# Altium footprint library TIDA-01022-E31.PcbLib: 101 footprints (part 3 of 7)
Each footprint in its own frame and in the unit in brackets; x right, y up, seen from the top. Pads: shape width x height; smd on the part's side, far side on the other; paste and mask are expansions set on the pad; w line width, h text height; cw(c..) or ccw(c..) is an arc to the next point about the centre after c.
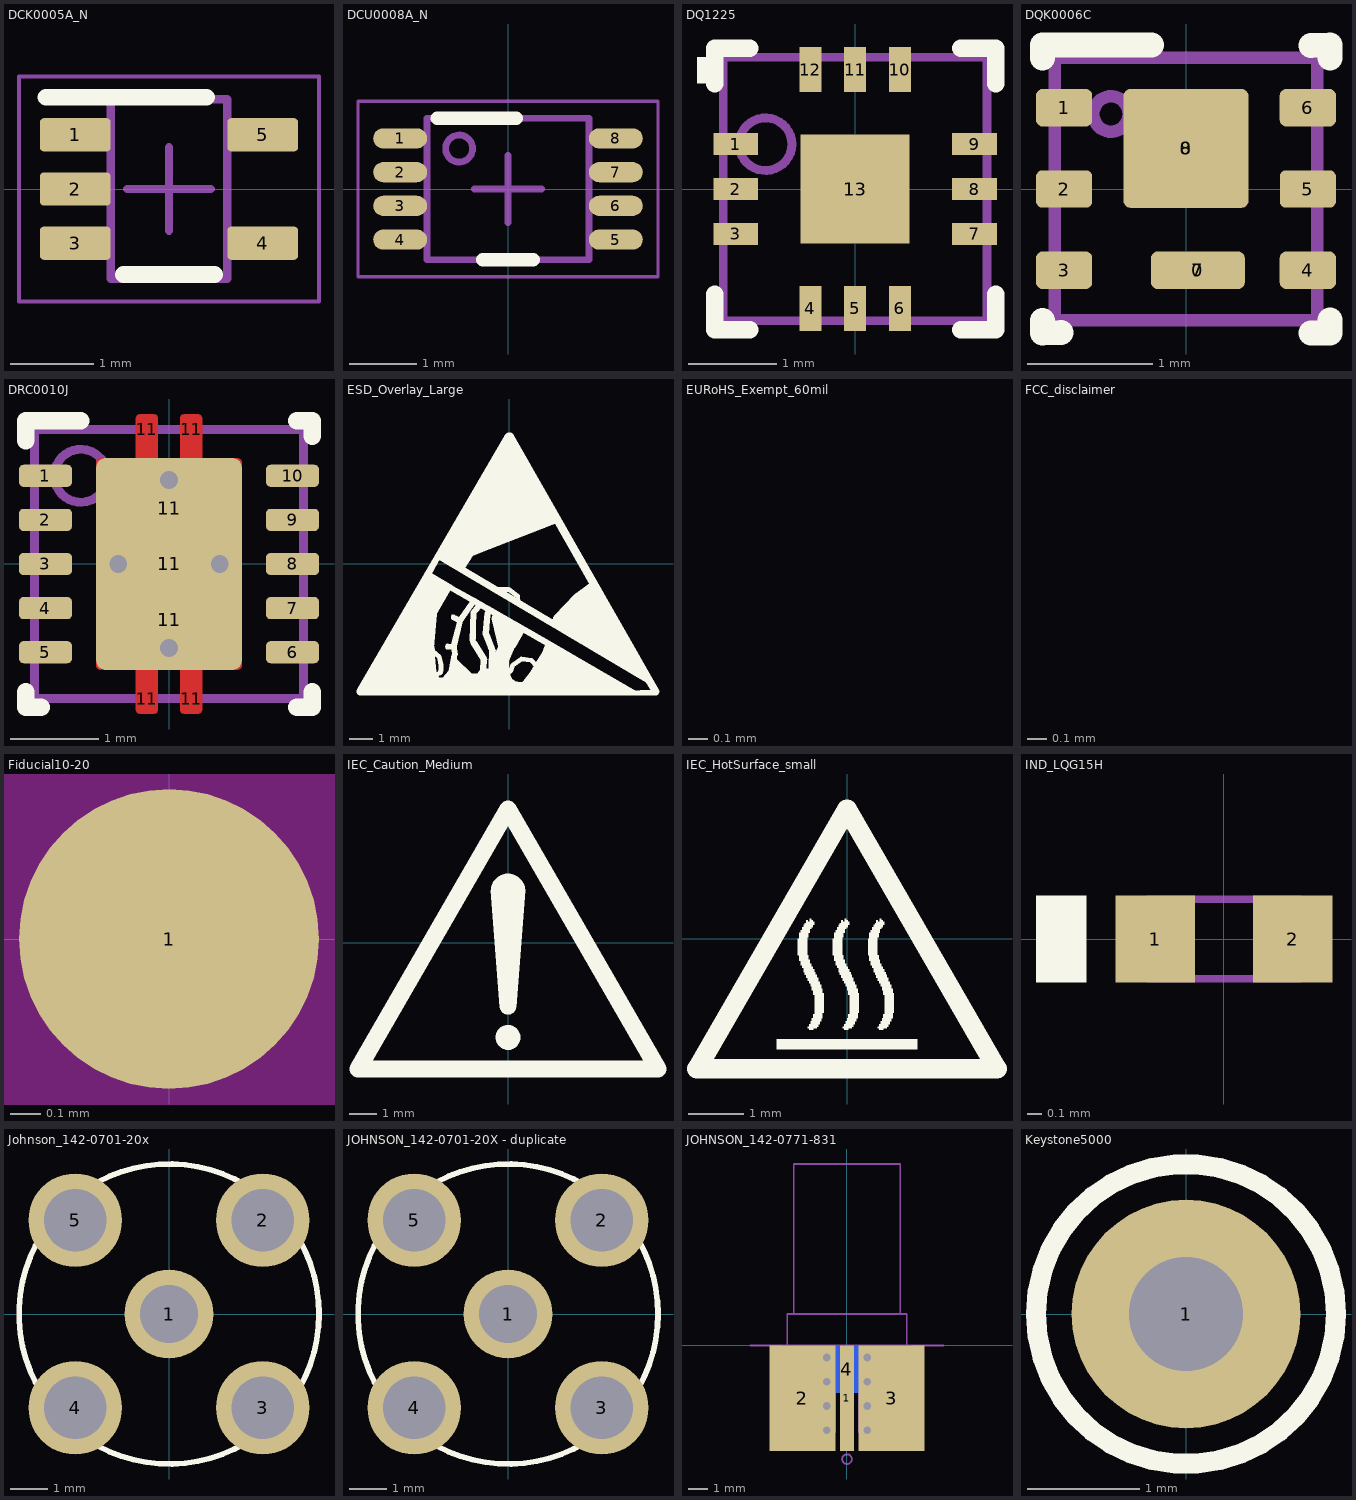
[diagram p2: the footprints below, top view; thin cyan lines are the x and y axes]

## DCK0005A_N [mm] "SOT353, 5-Leads, Body 2x1.3mm, Pitch 0.65mm, Lead Span 2.1mm, IPC Medium Density"
height 1.1
pads (5):
  rrect25% 0.85x0.4 smd: 1(10.178,0.65) 2(10.178,0) 3(10.178,-0.65) 4(12.428,-0.65) 5(12.428,0.65)
Top Overlay:
  lines w0.2: 9.828,1.1 11.753,1.1 ; 10.753,-1.025 11.853,-1.025
Mechanical 5:
  lines w0.1: 10.603,-1.075 12.003,-1.075 12.003,1.075 10.603,1.075 10.603,-1.075
  lines w0.127: 10.438,0.762 10.45,0.762 ; 10.592,-0.763 10.45,-0.763 10.438,-0.763 10.344,-0.763 10.16,-0.763 10.16,-0.538 10.344,-0.538 10.438,-0.538 10.45,-0.538 10.592,-0.538 ; 10.592,-0.113 10.45,-0.113 10.438,-0.113 10.344,-0.113 10.16,-0.113 10.16,0.112 10.344,0.112 10.438,0.112 10.45,0.112 10.592,0.112 ; 10.592,0.537 10.45,0.537 10.438,0.537 10.344,0.537 10.16,0.537 10.16,0.762 10.344,0.762 10.592,0.762 ; 12.014,-0.763 12.15,-0.763 12.162,-0.763 12.256,-0.763 12.44,-0.763 12.44,-0.538 12.256,-0.538 12.162,-0.538 12.15,-0.538 12.014,-0.538 ; 12.014,0.537 12.15,0.537 12.162,0.537 12.256,0.537 12.44,0.537 12.44,0.762 12.256,0.762 12.162,0.762 12.15,0.762 12.014,0.762
  text ".Designator" at 11.046,0.618 h0.51
Mechanical 15:
  lines w0.05: 9.503,-1.35 13.103,-1.35 13.103,1.35 9.503,1.35 9.503,-1.35
  lines w0.1: 10.803,0 11.803,0 ; 11.303,-0.5 11.303,0.5
3D body "DCK0005A.stp": height 0.95, standoff 0, extent 10.163,-1 12.443,1

## DCU0008A_N [mm] "TSSOP, 8-Leads, Body 2x2.3mm, Pitch 0.5mm, IPC Medium Density"
height 0.9
pads (8):
  oval 0.8x0.3 smd: 1(-1.6,0.75) 2(-1.6,0.25) 3(-1.6,-0.25) 4(-1.6,-0.75) 5(1.6,-0.75) 6(1.6,-0.25) 7(1.6,0.25) 8(1.6,0.75)
Top Overlay:
  lines w0.2: -1.05,1.05 0.125,1.05 ; -0.375,-1.05 0.375,-1.05
Mechanical 5:
  circle w0.1: c-0.725,0.6 r0.2
  lines w0.1: -1.2,-1.05 1.2,-1.05 1.2,1.05 -1.2,1.05 -1.2,-1.05
  text ".Designator" at 0.635,-0.127 h0.51
Mechanical 15:
  lines w0.05: -2.225,-1.3 -2.225,1.3 2.225,1.3 2.225,-1.3 -2.225,-1.3
  lines w0.1: -0.5,0 0.5,0 ; 0,-0.5 0,0.5
3D body "DCU0008A.stp": height 0.9, standoff 0, extent -1.561,-1 1.561,1

## DQ1225 [mm] "SMD, 12-Leads, Body 3x3mm"
height 0.89
pads (13):
  rect 0.51x0.25 smd: 1(-1.36,0.51) 2(-1.36,0) 3(-1.36,-0.51) 7(1.36,-0.51) 8(1.36,0) 9(1.36,0.51)
  rect 0.25x0.51 smd: 4(-0.51,-1.36) 5(0,-1.36) 6(0.51,-1.36) 10(0.51,1.36) 11(0,1.36) 12(-0.51,1.36)
  rect 1.24x1.24 smd: 13(0,0)
Top Overlay:
  rectangle: -1.8,1.2 -1.6,1.5
  lines w0.2: -1.6,-1.2 -1.6,-1.6 -1.2,-1.6 ; -1.6,1.2 -1.6,1.6 -1.2,1.6 ; 1.2,-1.6 1.6,-1.6 1.6,-1.2 ; 1.2,1.6 1.6,1.6 1.6,1.2
Mechanical 5:
  circle w0.1: c-1.02,0.51 r0.3
  lines w0.1: -1.5,-1.5 -1.5,1.5 1.5,1.5 1.5,-1.5 -1.5,-1.5
  text ".Designator" at -1.02,-0.51 h0.51
3D body: height 0.89, standoff 0, extent -1.5,-1.5 1.5,1.5
3D body: height 0.89, standoff 0.89, extent -1.319,0.211 -0.721,0.809

## DQK0006C [mm] "WSON"
height 0.8
pads (10):
  rrect50% 0.9x0.86 on Top Paste: 0(0,0.325)
  rrect50% 0.7x0.29 on Top Paste: 0(0.095,-0.65)
  rrect33% 0.45x0.3 smd: 1(-0.975,0.65) 2(-0.975,0) 3(-0.975,-0.65) 4(0.975,-0.65) 5(0.975,0) 6(0.975,0.65)
  rrect33% 0.75x0.3 smd paste-0.15: 7(0.095,-0.65)
  rrect11% 1x0.95 smd paste-0.5: 8(0,0.325)
Top Overlay:
  lines w0.2: -1.15,-1.05 -1.15,-1.15 -1,-1.15 ; -1.15,1.05 -1.15,1.15 -0.275,1.15 ; 1,-1.15 1.15,-1.15 1.15,-1.05 ; 1,1.15 1.15,1.15 1.15,1.05
Mechanical 5:
  circle w0.1: c-0.6,0.6 r0.141
  lines w0.1: -1.05,-1.05 1.05,-1.05 1.05,1.05 -1.05,1.05 -1.05,-1.05
  text ".Designator" at 0.267,-0.533 h0.51
3D body "DQK0006C.stp": height 0.82, standoff 0, extent -1,-1 1,1

## DRC0010J [mm] "SON, 10-Leads, Body 3x3mm, Pitch 0.5mm, Thermal Pad 2.4x1.65mm, TI Recommended"
height 1
pads (17):
  rrect40% 0.6x0.25 smd: 1(-1.4,1) 2(-1.4,0.5) 3(-1.4,0) 4(-1.4,-0.5) 5(-1.4,-1) 6(1.4,-1) 7(1.4,-0.5) 8(1.4,0) 9(1.4,0.5) 10(1.4,1)
  rrect50% 0.25x0.34 on Top Paste: 11(-0.25,-1.53) 11(-0.25,1.53) 11(0.25,-1.53) 11(0.25,1.53)
  rrect50% 1.5x1.06 on Top Paste: 11(0,-0.63) 11(0,0.63)
  rrect12% 1.65x2.4 smd paste-1 mask-2: 11(0,0)
via 0,-0.95 diameter 0.406 hole 0.203
via 0,0.95 diameter 0.406 hole 0.203
via -0.575,0 diameter 0.406 hole 0.203
via 0.575,0 diameter 0.406 hole 0.203
Top Layer:
  region: -0.775,-1.2 -0.375,-1.2 -0.375,-1.65 -0.375,-1.66 -0.367,-1.678 -0.353,-1.692 -0.335,-1.7 -0.325,-1.7 -0.175,-1.7 -0.165,-1.7 -0.147,-1.692 -0.133,-1.678 -0.125,-1.66 -0.125,-1.65 -0.125,-1.2 0.125,-1.2 0.125,-1.65 0.125,-1.66 0.133,-1.678 0.147,-1.692 0.165,-1.7 0.175,-1.7 0.325,-1.7 0.335,-1.7 0.353,-1.692 0.367,-1.678 0.375,-1.66 0.375,-1.65 0.375,-1.2 0.775,-1.2 0.785,-1.2 0.803,-1.192 0.817,-1.178 0.825,-1.16 0.825,-1.15 0.825,1.15 0.825,1.16 0.817,1.178 0.803,1.192 0.785,1.2 0.775,1.2 0.375,1.2 0.375,1.65 0.375,1.66 0.367,1.678 0.353,1.692 0.335,1.7 0.325,1.7 0.175,1.7 0.165,1.7 0.147,1.692 0.133,1.678 0.125,1.66 0.125,1.65 0.125,1.2 -0.125,1.2 -0.125,1.65 -0.125,1.66 -0.133,1.678 -0.147,1.692 -0.165,1.7 -0.175,1.7 -0.325,1.7 -0.335,1.7 -0.353,1.692 -0.367,1.678 -0.375,1.66 -0.375,1.65 -0.375,1.2 -0.775,1.2 -0.785,1.2 -0.803,1.192 -0.817,1.178 -0.825,1.16 -0.825,1.15 -0.825,-1.15 -0.825,-1.16 -0.817,-1.178 -0.803,-1.192 -0.785,-1.2
Top Overlay:
  lines w0.2: -1.625,-1.45 -1.625,-1.625 -1.45,-1.625 ; -1.625,1.4 -1.625,1.625 -1,1.625 ; 1.45,-1.625 1.625,-1.625 1.625,-1.45 ; 1.45,1.625 1.625,1.625 1.625,1.45
Mechanical 5:
  circle w0.1: c-1,1 r0.3
  lines w0.1: -1.525,-1.525 -1.525,1.525 1.525,1.525 1.525,-1.525 -1.525,-1.525
  text ".Designator" at 0.78,0.097 h0.51
3D body "DRC0010J.stp": height 0.77, standoff 0, extent -1.5,-1.5 1.5,1.5

## ESD_Overlay_Large [mm]
height 1.45
Top Overlay:
  drawing of 13628 lines, arcs and shapes, not listed

## EURoHS_Exempt_60mil [mm] "EU RoHS Exempt symbol"
height 1.45
Top Overlay:
  text "RoHS Exempt" at -7.745,174.843 h1.52

## FCC_disclaimer [mm]
height 9.53
Top Overlay:
  text "For evaluation only; not FCC approved for resale." at -18.311,34.714 h1.52

## Fiducial10-20 [mm]
height 9.53
pads (1):
  round 1 smd mask+0.5: 1(0,0)
Top Layer keep-out:
  circle w1.178: c0,0 r0.5

## IEC_Caution_Medium [mm]
Top Overlay:
  circle w0.305: c0,-2.337 r0.152
  circle w0.635: c0,1.905 r0.318
  circle w0.457: c0,-3.48 r0.229
  region: -0.635,1.93 0.635,1.93 0.305,-2.362 -0.305,-2.362
  lines w0.635: -5.512,-4.635 5.512,-4.635 0,4.911 -5.512,-4.635

## IEC_HotSurface_small [mm]
Top Overlay:
  drawing of 10 lines, arcs and shapes, not listed

## IND_LQG15H [mm] "MuRata"
height 0.55
pads (2):
  rect 0.55x0.6 smd: 1(-0.475,0) 2(0.475,0)
Top Overlay:
  rectangle: -1.3,-0.3 -0.95,0.3
Mechanical 5:
  rectangle: -0.7,-0.275 -0.525,0.275
  lines w0.05: -0.525,-0.275 -0.525,0.275 0.525,0.275 0.525,-0.275 -0.525,-0.275
  text ".Designator" at -2.303,-0.247 h0.51
3D body: height 0.55, standoff 0.54, extent -0.274,-0.275 -0.001,0.274
3D body: height 0.55, standoff 0, extent 0.276,-0.274 0.524,0.274
3D body: height 0.54, standoff 0, extent -0.274,-0.274 0.274,0.274
3D body: height 0.55, standoff 0, extent -0.524,-0.274 -0.276,0.274

## Johnson_142-0701-20x [mil] "Johnson Components recommended land pattern"
height 375
pads (5):
  round 95 hole 62: 1(0,0)
  round 100 hole 67: 2(100,100) 3(100,-100) 4(-100,-100) 5(-100,100)
Top Overlay:
  circle w6: c0,0 r160
Mechanical 5:
  circle w5: c0,0 r160
  text ".Designator" at -22.72,-13.85 h20
3D body "Emerson_142-0701-201.stp": height 375, standoff -155, extent -155.99,-155.8 156.01,155.8

## JOHNSON_142-0701-20X - duplicate [mil]
pads (5):
  round 95 hole 62: 1(0,0)
  round 100 hole 67: 2(100,100) 3(100,-100) 4(-100,-100) 5(-100,100)
Top Overlay:
  circle w6: c0,0 r160
Mechanical 5:
  circle w5: c0,0 r160
  text ".Designator" at -17.5,49.39 h20
3D body "Emerson_142-0701-201.stp": height 375, standoff -155, extent -155.99,-155.8 156.01,155.8

## JOHNSON_142-0771-831 [mil]
pads (12):
  rect 28.5x218 smd: 1(0,-109)
  rect 135.75x218 smd: 2(-92.12,-109) 3(92.13,-109)
  rect 270x97.5 smd far side: 4(0,-48.75)
  round 16 hole 16: ""(-42,-175) ""(-42,-125) ""(-42,-75) ""(-42,-25) ""(42,-175) ""(42,-125) ""(42,-75) ""(42,-25)
Mechanical 1:
  lines w3.94: -200,0 200,0
Mechanical 5:
  circle w3.94: c0,-235 r10
  lines w3.94: -110,65 -110,375 110,375 110,65 ; -79.36,0 -79.36,-179 ; -25,-65 25,-65 ; -25,-60 25,-60 ; -25,0 -25,-179 -79.36,-179 ; -7.5,0 -7.5,-22.5 ccw(c0,-22.5) 7.5,-22.5 7.5,0 ; 25,0 25,-179 79.36,-179 ; 79.36,0 79.36,-179 ; -114.35,-179 -123.5,-179 -123.5,65 123.5,65 123.5,-179 114.34,-179 ; -114.35,-179 -114.35,0 114.34,0 114.34,-179 ; -114.35,-179 -79.36,-179 ; 79.36,-179 114.34,-179
  text ".Designator" at -40.79,-210.73 h20
3D body "142-0771-831.stp": height 130.9, standoff -116, extent -123.5,-179 123.47,375

## Keystone5000 [mil] "For Keystone 500x miniature loop terminals"
height 181.1
pads (1):
  round 80 hole 40: 1(0,0)
Top Overlay:
  circle w7: c0,0 r52.5
Mechanical 5:
  circle w3.94: c0,0 r52.5
  text ".Designator" at -9,36 h20
3D body "Keystone_5000.stp": height 181.97, standoff -118.11, extent -49,-49 49.04,49.24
